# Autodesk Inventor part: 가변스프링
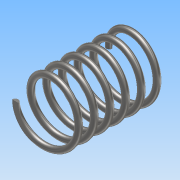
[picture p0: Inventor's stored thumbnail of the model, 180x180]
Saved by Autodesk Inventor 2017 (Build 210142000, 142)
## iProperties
Part Number: 가변스프링
Material: 스테인레스 스틸
Document SubType Name: Modeling
Designer: user
Density: 8 g/cm^3
Appearance: 반연마
Mass: 8.40798 g
Surface Area: 21.2967 cm^2
Volume: 1.051 cm^3
Author: user
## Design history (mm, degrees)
sketch "스케치1"
  geometry: L1 (-9, 30.5)-(0, 30.5); L2 (0, 30.5)-(0, 0); L3 (0, 0)-(-9, 0); L4 (-9, 0)-(-9, 30.5); C1 r 1 at (-9, 0); 1 further point
  constraints: 8 end point, 2 coincident, 2 parallel, 1 centre point, 1 horizontal, 1 perpendicular
  dimensions: "d0" = 2 diameter of C1; "d1" = 18 diameter of L4 L2; "d2" = 30.5 distance between parallel lines of L3 L1 (derived)
feature "코일1" sketch "스케치1" pitch "d3" = 10; turns "d5" = 6; dims "d4" = 30.5 (= d2), "d6" = 0, angle "d7" = 90 deg, angle "d8" = 90 deg, "d9" = 0, "d10" = 0
sketch "스케치2"
  geometry: L1 (8, 0)-(10, 0) reference; 1 further point
  constraints: 1 horizontal alignment
extrude "돌출1" cut sketch "스케치2" stored distance "d11" = 10; taper "d12" = 0 deg
node "작업 평면1"
sketch "스케치3"
  geometry: L1 (1, 0)-(-1, 0) reference; 1 further point
  constraints: 1 horizontal alignment
extrude "돌출2" cut sketch "스케치3" stored distance "d13" = 10; taper "d14" = 0 deg
node "솔리드1"
node "절단 모서리 투영1"
node "절단 모서리 투영2"
